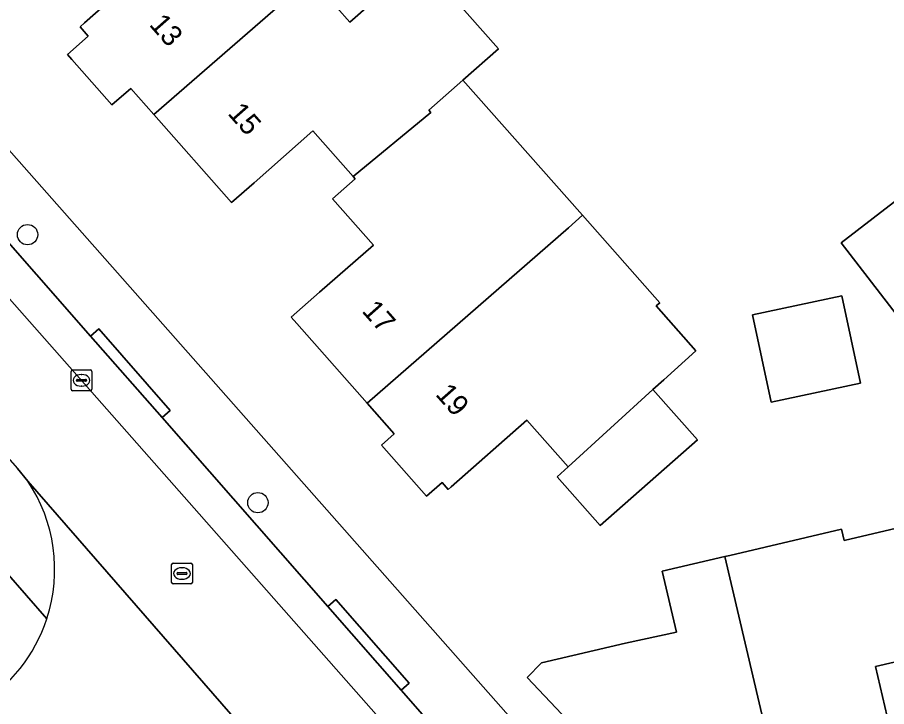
# Model space of a CAD drawing. Extents: x 157320 to 158835, y 386650 to 388491.
# Drawn here: x 157647.93 to 157689.7, y 387837.43 to 387870.56 of the extents above; entities that cross this region are included whole.
import ezdxf

# ---------------------------------------------------------------- set-up
doc = ezdxf.new("R2010")
doc.units = 0
for name, color, linetype in [('IMGEO_Boom', 7, 'Continuous'), ('IMGEO_Erf', 7, 'Continuous'), ('IMGEO_Kolk', 7, 'Continuous'), ('IMGEO_Pand', 7, 'Continuous'), ('IMGEO_Pand_nummerreeks', 7, 'Continuous'), ('IMGEO_Parkeervlak_open', 7, 'Continuous'), ('IMGEO_Rijbaan_lokaal_open', 7, 'Continuous'), ('IMGEO_Rioolput', 7, 'Continuous'), ('IMGEO_Voetpad_open', 7, 'Continuous')]:
    doc.layers.add(name, color=color, linetype=linetype)

msp = doc.modelspace()

# ---------------------------------------------------------------- linework, layer by layer
at = {"layer": 'IMGEO_Boom'}
for centre in [(157648.423, 387860.12), (157659.488, 387847.237)]:
    msp.add_circle(centre, 0.489, dxfattribs=at)
at = {"layer": 'IMGEO_Erf'}
for points in [[(157611.28, 387905.251), (157676.491, 387831.375), (157676.979, 387830.83), (157677.515, 387830.331), (157678.092, 387829.881), (157678.708, 387829.485), (157679.356, 387829.145), (157680.033, 387828.865), (157680.731, 387828.646), (157681.446, 387828.491), (157682.173, 387828.4), (157682.904, 387828.374), (157683.635, 387828.414), (157684.359, 387828.519), (157684.789, 387828.613), (157729.457, 387839.094), (157721.261, 387874.483)], [(157662.03, 387872.467), (157663.908, 387870.338), (157667.282, 387873.316), (157671.047, 387869.053), (157669.343, 387867.549), (157675.08, 387861.051), (157678.796, 387856.842), (157678.631, 387856.696), (157680.533, 387854.542), (157678.999, 387853.135), (157678.473, 387852.671), (157680.608, 387850.252), (157675.942, 387846.134), (157673.866, 387848.485), (157674.396, 387848.953), (157672.411, 387851.201), (157668.774, 387847.991), (157668.639, 387847.871), (157668.345, 387848.205), (157667.596, 387847.544), (157665.425, 387850.003), (157666.033, 387850.54), (157664.735, 387852.012), (157661.357, 387855.843), (157661.085, 387856.159), (157662.454, 387857.352), (157665.042, 387859.607), (157663.07, 387861.842), (157664.16, 387862.804), (157664.067, 387862.909), (157662.132, 387865.102), (157659.315, 387862.616), (157658.22, 387861.661), (157654.485, 387865.897), (157653.379, 387867.152), (157652.465, 387866.367), (157650.542, 387868.544), (157650.337, 387868.776), (157651.341, 387869.663), (157650.943, 387870.112), (157651.161, 387870.304), (157654.725, 387873.451)], [(157691.851, 387839.993), (157689.16, 387839.362), (157690.285, 387834.558), (157684.618, 387833.182), (157682.822, 387832.769), (157683.099, 387831.581), (157680.066, 387830.875), (157679.801, 387832.028), (157679.125, 387831.901), (157678.367, 387835.172), (157676.317, 387834.707), (157672.433, 387838.837), (157673.123, 387839.541), (157677.151, 387840.482), (157679.604, 387841.014), (157678.918, 387843.945), (157681.926, 387844.649), (157682.161, 387844.704), (157687.529, 387845.961), (157687.657, 387845.414), (157690.447, 387846.067)]]:
    msp.add_lwpolyline(points, dxfattribs=at)
for points in [[(157691.569, 387862.849), (157694.326, 387859.269), (157690.271, 387856.146), (157687.514, 387859.725)], [(157687.552, 387857.179), (157688.446, 387852.979), (157684.155, 387852.065), (157683.26, 387856.265)]]:
    msp.add_lwpolyline(points, close=True, dxfattribs=at)
at = {"layer": 'IMGEO_Kolk'}
for p, q in [((157650.587, 387853.617), (157651.439, 387853.617)), ((157650.512, 387852.691), (157650.512, 387853.543)), ((157651, 387853.397), (157651.025, 387853.397)), ((157651.513, 387853.543), (157651.513, 387852.691)), ((157650.771, 387853.111), (157650.771, 387853.123)), ((157651.209, 387853.074), (157650.811, 387853.074)), ((157650.814, 387853.16), (157651.212, 387853.16)), ((157651.023, 387852.837), (157650.998, 387852.837)), ((157651.255, 387853.123), (157651.255, 387853.111)), ((157651.439, 387852.617), (157650.587, 387852.617))]:
    msp.add_line(p, q, dxfattribs=at)
for points in [[(157650.587, 387853.617), (157651.439, 387853.617)], [(157650.512, 387852.691), (157650.512, 387853.543)], [(157651.513, 387853.543), (157651.513, 387852.691)], [(157651.439, 387852.617), (157650.587, 387852.617)]]:
    msp.add_lwpolyline(points, dxfattribs=at)
for centre, radius, start, end in [((157650.589, 387853.541), 0.0765, 91.552, 178.448), ((157650.589, 387853.541), 0.0765, 91.552, 178.448), ((157651.437, 387853.541), 0.0765, 1.552, 88.448), ((157651.437, 387853.541), 0.0765, 1.552, 88.448), ((157650.811, 387853.12), 0.0403, 85.8775, 175.7526), ((157650.808, 387853.11), 0.0366, 178.938, 274.7102), ((157651.212, 387853.117), 0.043, 264.8664, 352.4533), ((157651.216, 387853.122), 0.0386, 1.7309, 96.639), ((157650.589, 387852.693), 0.0765, 181.552, 268.448), ((157650.589, 387852.693), 0.0765, 181.552, 268.448), ((157651.437, 387852.693), 0.0765, 271.552, 358.448), ((157651.437, 387852.693), 0.0765, 271.552, 358.448)]:
    msp.add_arc(centre, radius, start, end, dxfattribs=at)
for centre, major_axis, ratio, start_param, end_param in [((157650.999, 387853.117), (-0.387, 0.002), 0.722429, 4.712389, 7.853982), ((157651.024, 387853.117), (-0.39, 0.002), 0.717154, 1.570796, 4.712389)]:
    msp.add_ellipse(centre, major_axis=major_axis, ratio=ratio, start_param=start_param, end_param=end_param, dxfattribs=at)
at = {"layer": 'IMGEO_Pand'}
for points in [[(157663.904, 387874.135), (157660.256, 387878.269), (157658.207, 387880.59), (157652.659, 387875.792), (157654.725, 387873.451), (157651.161, 387870.304), (157650.943, 387870.112), (157651.341, 387869.663), (157650.337, 387868.776), (157650.542, 387868.544), (157652.465, 387866.367), (157653.379, 387867.152), (157654.485, 387865.897), (157662.03, 387872.467)], [(157669.343, 387867.549), (157671.047, 387869.053), (157667.282, 387873.316), (157663.908, 387870.338), (157662.03, 387872.467), (157654.485, 387865.897), (157658.22, 387861.661), (157659.315, 387862.616), (157662.132, 387865.102), (157664.067, 387862.909), (157667.795, 387865.993), (157667.701, 387866.099)], [(157674.41, 387860.452), (157675.08, 387861.051), (157669.343, 387867.549), (157667.701, 387866.099), (157667.795, 387865.993), (157664.067, 387862.909), (157664.16, 387862.804), (157663.07, 387861.842), (157665.042, 387859.607), (157662.454, 387857.352), (157661.085, 387856.159), (157661.357, 387855.843), (157664.735, 387852.012)], [(157687.514, 387859.725), (157690.271, 387856.146), (157694.326, 387859.269), (157691.569, 387862.849)], [(157678.473, 387852.671), (157678.999, 387853.135), (157680.533, 387854.542), (157678.631, 387856.696), (157678.796, 387856.842), (157675.08, 387861.051), (157674.41, 387860.452), (157664.735, 387852.012), (157666.033, 387850.54), (157665.425, 387850.003), (157667.596, 387847.544), (157668.345, 387848.205), (157668.639, 387847.871), (157668.774, 387847.991), (157672.411, 387851.201), (157674.396, 387848.953)], [(157684.155, 387852.065), (157688.446, 387852.979), (157687.552, 387857.179), (157683.26, 387856.265)], [(157674.396, 387848.953), (157673.866, 387848.485), (157675.942, 387846.134), (157680.608, 387850.252), (157678.473, 387852.671)], [(157691.851, 387839.993), (157690.447, 387846.067), (157687.657, 387845.414), (157687.529, 387845.961), (157682.161, 387844.704), (157681.926, 387844.649), (157684.618, 387833.182), (157690.285, 387834.558), (157689.16, 387839.362)], [(157684.618, 387833.182), (157681.926, 387844.649), (157678.918, 387843.945), (157679.604, 387841.014), (157677.151, 387840.482), (157673.123, 387839.541), (157672.433, 387838.837), (157676.317, 387834.707), (157678.367, 387835.172), (157679.125, 387831.901), (157679.801, 387832.028), (157680.066, 387830.875), (157683.099, 387831.581), (157682.822, 387832.769)]]:
    msp.add_lwpolyline(points, close=True, dxfattribs=at)
at = {"layer": 'IMGEO_Parkeervlak_open'}
for points in [[(157608.833, 387900.938), (157673.92, 387827.143)], [(157673.331, 387830.291), (157666.378, 387838.229), (157662.854, 387842.247), (157654.888, 387851.328), (157651.453, 387855.244), (157643.765, 387864.008)]]:
    msp.add_lwpolyline(points, dxfattribs=at)
at = {"layer": 'IMGEO_Rijbaan_lokaal_open'}
for points in [[(157729.55, 387834.104), (157728.562, 387833.876), (157724.892, 387833.031), (157714.68, 387830.684), (157683.612, 387823.423), (157683.417, 387823.394), (157683.222, 387823.368), (157682.956, 387823.339), (157682.032, 387823.293), (157681.107, 387823.329), (157680.189, 387823.447), (157679.285, 387823.647), (157678.403, 387823.927), (157677.549, 387824.285), (157676.731, 387824.718), (157675.955, 387825.222), (157675.226, 387825.793), (157674.552, 387826.427), (157673.92, 387827.143), (157608.833, 387900.938)], [(157602.837, 387900.03), (157604.73, 387897.915), (157647.931, 387848.881), (157648.432, 387848.271), (157660.135, 387834.829), (157671.431, 387822.03)], [(157660.135, 387834.829), (157648.432, 387848.271)]]:
    msp.add_lwpolyline(points, dxfattribs=at)
for centre, start, end in [((157642.117, 387844.025), 341.8935, 33.9175), ((157642.114, 387844.015), 300.8553, 341.9691)]:
    msp.add_arc(centre, 7.609, start, end, dxfattribs=at)
at = {"layer": 'IMGEO_Rioolput'}
for p, q in [((157655.341, 387843.405), (157655.341, 387844.257)), ((157655.416, 387844.331), (157656.268, 387844.331)), ((157655.829, 387844.111), (157655.854, 387844.111)), ((157656.342, 387844.257), (157656.342, 387843.405)), ((157655.6, 387843.825), (157655.6, 387843.837)), ((157656.038, 387843.788), (157655.64, 387843.788)), ((157655.643, 387843.874), (157656.041, 387843.874)), ((157656.084, 387843.837), (157656.084, 387843.825)), ((157656.268, 387843.331), (157655.416, 387843.331)), ((157655.852, 387843.551), (157655.827, 387843.551))]:
    msp.add_line(p, q, dxfattribs=at)
for points in [[(157655.341, 387843.405), (157655.341, 387844.257)], [(157655.416, 387844.331), (157656.268, 387844.331)], [(157656.342, 387844.257), (157656.342, 387843.405)], [(157656.268, 387843.331), (157655.416, 387843.331)]]:
    msp.add_lwpolyline(points, dxfattribs=at)
for centre, radius, start, end in [((157655.418, 387844.255), 0.0765, 91.552, 178.448), ((157655.418, 387844.255), 0.0765, 91.552, 178.448), ((157656.266, 387844.255), 0.0765, 1.552, 88.448), ((157656.266, 387844.255), 0.0765, 1.552, 88.448), ((157655.64, 387843.834), 0.0403, 85.8775, 175.7526), ((157655.637, 387843.824), 0.0366, 178.938, 274.7102), ((157656.041, 387843.831), 0.043, 264.8664, 352.4533), ((157656.045, 387843.836), 0.0386, 1.7309, 96.639), ((157655.418, 387843.407), 0.0765, 181.552, 268.448), ((157655.418, 387843.407), 0.0765, 181.552, 268.448), ((157656.266, 387843.407), 0.0765, 271.552, 358.448), ((157656.266, 387843.407), 0.0765, 271.552, 358.448)]:
    msp.add_arc(centre, radius, start, end, dxfattribs=at)
for centre, major_axis, ratio, start_param, end_param in [((157655.828, 387843.831), (-0.387, 0.002), 0.722429, 4.712389, 7.853982), ((157655.853, 387843.831), (-0.39, 0.002), 0.717154, 1.570796, 4.712389)]:
    msp.add_ellipse(centre, major_axis=major_axis, ratio=ratio, start_param=start_param, end_param=end_param, dxfattribs=at)
at = {"layer": 'IMGEO_Voetpad_open'}
for points in [[(157676.491, 387831.375), (157611.28, 387905.251)], [(157599.154, 387898.545), (157631.299, 387862.056), (157646.328, 387844.995), (157646.404, 387845.018), (157649.35, 387841.66)], [(157643.765, 387864.008), (157651.453, 387855.244), (157651.839, 387855.585), (157655.271, 387851.667), (157654.888, 387851.328), (157662.854, 387842.247), (157663.23, 387842.58), (157666.752, 387838.56), (157666.378, 387838.229), (157673.331, 387830.291)], [(157648.432, 387848.271), (157647.931, 387848.881)], [(157649.35, 387841.66), (157646.404, 387845.018), (157646.328, 387844.995)]]:
    msp.add_lwpolyline(points, dxfattribs=at)
for points in [[(157651.839, 387855.585), (157651.453, 387855.244), (157654.888, 387851.328), (157655.271, 387851.667)], [(157663.23, 387842.58), (157662.854, 387842.247), (157666.378, 387838.229), (157666.752, 387838.56)]]:
    msp.add_lwpolyline(points, close=True, dxfattribs=at)
for centre, start, end in [((157642.117, 387844.025), 341.8935, 33.9175), ((157642.114, 387844.015), 300.8553, 341.9691)]:
    msp.add_arc(centre, 7.609, start, end, dxfattribs=at)

# ---------------------------------------------------------------- texts
at = {"layer": 'IMGEO_Pand_nummerreeks'}
for s, rotation, p in [('13', 311.4304, (157654.23, 387870.197)), ('15', 311.4304, (157657.998, 387865.928)), ('17', 311.4361, (157664.447, 387856.429)), ('19', 311.4361, (157667.981, 387852.426))]:
    msp.add_text(s, height=1, rotation=rotation, dxfattribs=at).set_placement(p)

doc.saveas('drawing.dxf')
